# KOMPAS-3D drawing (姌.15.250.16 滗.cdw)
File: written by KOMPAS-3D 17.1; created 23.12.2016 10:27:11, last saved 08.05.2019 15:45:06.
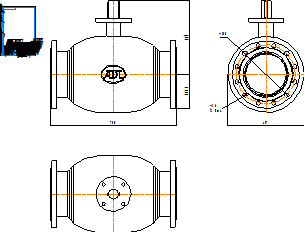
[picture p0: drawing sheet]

Sheet 1: A4, portrait

Title block, sheet 1: name: КШ.15.250.16 фф; material: Внимание! Данный продукт является объектом авторского права ООО «Торговый Дом АДЛ». / Запрещается изменение, копирование, распространение / (в том числе путем копирования на другие сайты и ресурсы в Интернете) / или любое иное использование информации и объектов без предварительного / согласия правообладателя (ООО «Торговый Дом АДЛ»).; sheets: 1; organisation: ООО "Торговый дом АДЛ"; sheet format: A4; stored path: C:\Users\tra\Desktop\2д чертежи\Шаровые краны БИВАЛ\КШ_Бивал_серия_14_15\KOMPAS_2D\КШ.15.250.16 фф.cdw

Views: Вид 1, Проекционный вид 2, Проекционный вид 3
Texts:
  Klimkovich
  ADL
Dimensions and other numbers on the sheet: 750; 441; 202,5; 457; 355; 26; 12 Отв.; 1:1; 1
